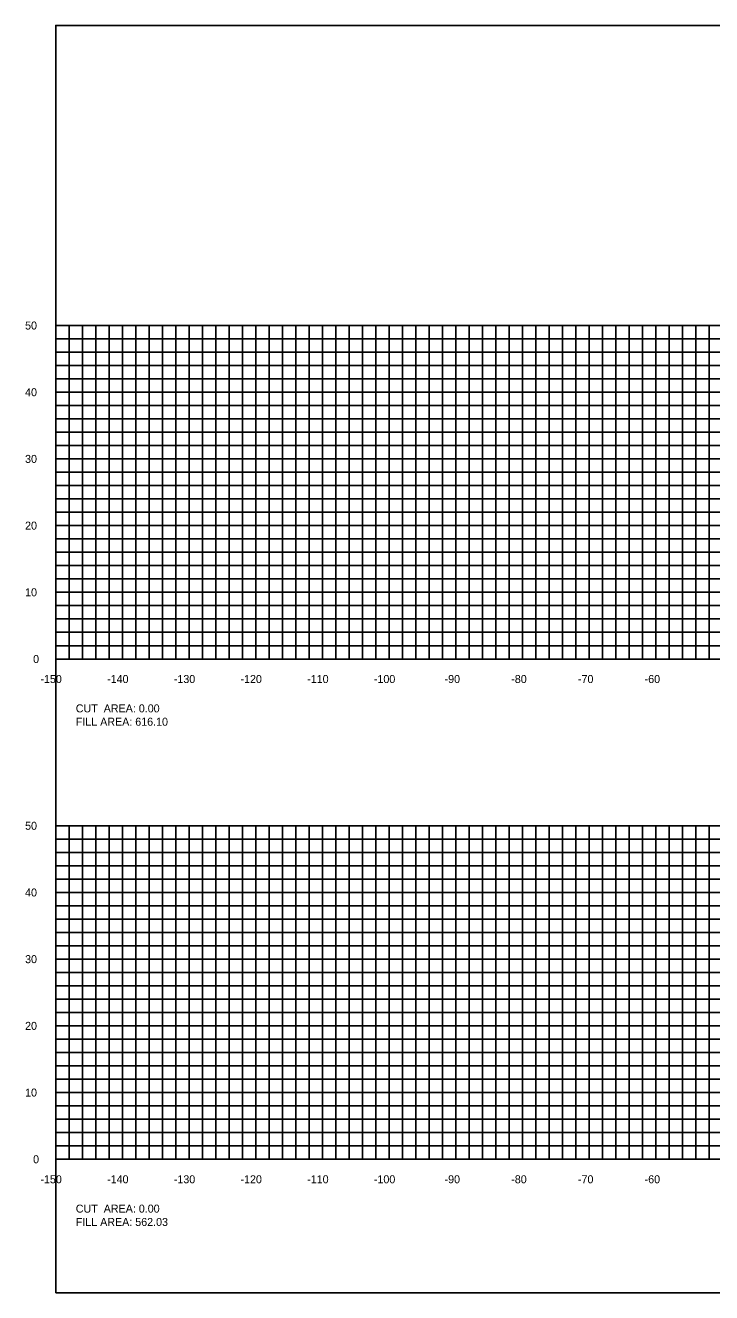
# Model space of a CAD drawing. Extents: x 1797714 to 1804825, y 249015 to 250269.
# Drawn here: x 1803156.4 to 1803259.4, y 250079.4 to 250269.4 of the extents above; entities that cross this region are included whole.
import ezdxf

# ---------------------------------------------------------------- set-up
doc = ezdxf.new("R2010")
doc.units = 0
for name, color, linetype in [('10', 7, 'Continuous'), ('31', 7, 'Continuous'), ('60', 7, 'Continuous'), ('ANNO-TXT', 7, 'Continuous'), ('Level 62', 7, 'Continuous')]:
    doc.layers.add(name, color=color, linetype=linetype)

msp = doc.modelspace()

# ---------------------------------------------------------------- linework, layer by layer
msp.add_lwpolyline([(1803161, 250079.43), (1803461, 250079.43), (1803461, 250269.43), (1803161, 250269.43)], close=True)
at = {"layer": '60'}
for p, q in [((1803160.94, 250224.43), (1803161, 250224.43)), ((1803161, 250174.43), (1803161, 250224.43)), ((1803160.94, 250214.43), (1803161, 250214.43)), ((1803160.94, 250204.43), (1803161, 250204.43)), ((1803160.94, 250194.43), (1803161, 250194.43)), ((1803160.94, 250184.43), (1803161, 250184.43)), ((1803160.94, 250174.43), (1803161, 250174.43)), ((1803161, 250174.43), (1803461, 250174.43)), ((1803161, 250174.37), (1803161, 250174.43)), ((1803171, 250174.37), (1803171, 250174.43)), ((1803181, 250174.37), (1803181, 250174.43)), ((1803191, 250174.37), (1803191, 250174.43)), ((1803201, 250174.37), (1803201, 250174.43)), ((1803211, 250174.37), (1803211, 250174.43)), ((1803221, 250174.37), (1803221, 250174.43)), ((1803231, 250174.37), (1803231, 250174.43)), ((1803241, 250174.37), (1803241, 250174.43)), ((1803251, 250174.37), (1803251, 250174.43)), ((1803160.94, 250149.43), (1803161, 250149.43)), ((1803161, 250099.43), (1803161, 250149.43)), ((1803160.94, 250139.43), (1803161, 250139.43)), ((1803160.94, 250129.43), (1803161, 250129.43)), ((1803160.94, 250119.43), (1803161, 250119.43)), ((1803160.94, 250109.43), (1803161, 250109.43)), ((1803160.94, 250099.43), (1803161, 250099.43)), ((1803161, 250099.43), (1803461, 250099.43)), ((1803161, 250099.37), (1803161, 250099.43)), ((1803171, 250099.37), (1803171, 250099.43)), ((1803181, 250099.37), (1803181, 250099.43)), ((1803191, 250099.37), (1803191, 250099.43)), ((1803201, 250099.37), (1803201, 250099.43)), ((1803211, 250099.37), (1803211, 250099.43)), ((1803221, 250099.37), (1803221, 250099.43)), ((1803231, 250099.37), (1803231, 250099.43)), ((1803241, 250099.37), (1803241, 250099.43)), ((1803251, 250099.37), (1803251, 250099.43))]:
    msp.add_line(p, q, dxfattribs=at)
at = {"layer": 'Level 62'}
for p, q in [((1803161, 250224.43), (1803461, 250224.43)), ((1803161, 250174.43), (1803161, 250224.43)), ((1803163, 250174.43), (1803163, 250224.43)), ((1803165, 250174.43), (1803165, 250224.43)), ((1803167, 250174.43), (1803167, 250224.43)), ((1803169, 250174.43), (1803169, 250224.43)), ((1803171, 250174.43), (1803171, 250224.43)), ((1803173, 250174.43), (1803173, 250224.43)), ((1803175, 250174.43), (1803175, 250224.43)), ((1803177, 250174.43), (1803177, 250224.43)), ((1803179, 250174.43), (1803179, 250224.43)), ((1803181, 250174.43), (1803181, 250224.43)), ((1803183, 250174.43), (1803183, 250224.43)), ((1803185, 250174.43), (1803185, 250224.43)), ((1803187, 250174.43), (1803187, 250224.43)), ((1803189, 250174.43), (1803189, 250224.43)), ((1803191, 250174.43), (1803191, 250224.43)), ((1803193, 250174.43), (1803193, 250224.43)), ((1803195, 250174.43), (1803195, 250224.43)), ((1803197, 250174.43), (1803197, 250224.43)), ((1803199, 250174.43), (1803199, 250224.43)), ((1803201, 250174.43), (1803201, 250224.43)), ((1803203, 250174.43), (1803203, 250224.43)), ((1803205, 250174.43), (1803205, 250224.43)), ((1803207, 250174.43), (1803207, 250224.43)), ((1803209, 250174.43), (1803209, 250224.43)), ((1803211, 250174.43), (1803211, 250224.43)), ((1803213, 250174.43), (1803213, 250224.43)), ((1803215, 250174.43), (1803215, 250224.43)), ((1803217, 250174.43), (1803217, 250224.43)), ((1803219, 250174.43), (1803219, 250224.43)), ((1803221, 250174.43), (1803221, 250224.43)), ((1803223, 250174.43), (1803223, 250224.43)), ((1803225, 250174.43), (1803225, 250224.43)), ((1803227, 250174.43), (1803227, 250224.43)), ((1803229, 250174.43), (1803229, 250224.43)), ((1803231, 250174.43), (1803231, 250224.43)), ((1803233, 250174.43), (1803233, 250224.43)), ((1803235, 250174.43), (1803235, 250224.43)), ((1803237, 250174.43), (1803237, 250224.43)), ((1803239, 250174.43), (1803239, 250224.43)), ((1803241, 250174.43), (1803241, 250224.43)), ((1803243, 250174.43), (1803243, 250224.43)), ((1803245, 250174.43), (1803245, 250224.43)), ((1803247, 250174.43), (1803247, 250224.43)), ((1803249, 250174.43), (1803249, 250224.43)), ((1803251, 250174.43), (1803251, 250224.43)), ((1803253, 250174.43), (1803253, 250224.43)), ((1803255, 250174.43), (1803255, 250224.43)), ((1803257, 250174.43), (1803257, 250224.43)), ((1803259, 250174.43), (1803259, 250224.43)), ((1803161, 250222.43), (1803461, 250222.43)), ((1803161, 250220.43), (1803461, 250220.43)), ((1803161, 250218.43), (1803461, 250218.43)), ((1803161, 250216.43), (1803461, 250216.43)), ((1803161, 250214.43), (1803461, 250214.43)), ((1803161, 250212.43), (1803461, 250212.43)), ((1803161, 250210.43), (1803461, 250210.43)), ((1803161, 250208.43), (1803461, 250208.43)), ((1803161, 250206.43), (1803461, 250206.43)), ((1803161, 250204.43), (1803461, 250204.43)), ((1803161, 250202.43), (1803461, 250202.43)), ((1803161, 250200.43), (1803461, 250200.43)), ((1803161, 250198.43), (1803461, 250198.43)), ((1803161, 250196.43), (1803461, 250196.43)), ((1803161, 250194.43), (1803461, 250194.43)), ((1803161, 250192.43), (1803461, 250192.43)), ((1803161, 250190.43), (1803461, 250190.43)), ((1803161, 250188.43), (1803461, 250188.43)), ((1803161, 250186.43), (1803461, 250186.43)), ((1803161, 250184.43), (1803461, 250184.43)), ((1803161, 250182.43), (1803461, 250182.43)), ((1803161, 250180.43), (1803461, 250180.43)), ((1803161, 250178.43), (1803461, 250178.43)), ((1803161, 250176.43), (1803461, 250176.43)), ((1803161, 250174.43), (1803461, 250174.43)), ((1803161, 250149.43), (1803461, 250149.43)), ((1803161, 250099.43), (1803161, 250149.43)), ((1803163, 250099.43), (1803163, 250149.43)), ((1803165, 250099.43), (1803165, 250149.43)), ((1803167, 250099.43), (1803167, 250149.43)), ((1803169, 250099.43), (1803169, 250149.43)), ((1803171, 250099.43), (1803171, 250149.43)), ((1803173, 250099.43), (1803173, 250149.43)), ((1803175, 250099.43), (1803175, 250149.43)), ((1803177, 250099.43), (1803177, 250149.43)), ((1803179, 250099.43), (1803179, 250149.43)), ((1803181, 250099.43), (1803181, 250149.43)), ((1803183, 250099.43), (1803183, 250149.43)), ((1803185, 250099.43), (1803185, 250149.43)), ((1803187, 250099.43), (1803187, 250149.43)), ((1803189, 250099.43), (1803189, 250149.43)), ((1803191, 250099.43), (1803191, 250149.43)), ((1803193, 250099.43), (1803193, 250149.43)), ((1803195, 250099.43), (1803195, 250149.43)), ((1803197, 250099.43), (1803197, 250149.43)), ((1803199, 250099.43), (1803199, 250149.43)), ((1803201, 250099.43), (1803201, 250149.43)), ((1803203, 250099.43), (1803203, 250149.43)), ((1803205, 250099.43), (1803205, 250149.43)), ((1803207, 250099.43), (1803207, 250149.43)), ((1803209, 250099.43), (1803209, 250149.43)), ((1803211, 250099.43), (1803211, 250149.43)), ((1803213, 250099.43), (1803213, 250149.43)), ((1803215, 250099.43), (1803215, 250149.43)), ((1803217, 250099.43), (1803217, 250149.43)), ((1803219, 250099.43), (1803219, 250149.43)), ((1803221, 250099.43), (1803221, 250149.43)), ((1803223, 250099.43), (1803223, 250149.43)), ((1803225, 250099.43), (1803225, 250149.43)), ((1803227, 250099.43), (1803227, 250149.43)), ((1803229, 250099.43), (1803229, 250149.43)), ((1803231, 250099.43), (1803231, 250149.43)), ((1803233, 250099.43), (1803233, 250149.43)), ((1803235, 250099.43), (1803235, 250149.43)), ((1803237, 250099.43), (1803237, 250149.43)), ((1803239, 250099.43), (1803239, 250149.43)), ((1803241, 250099.43), (1803241, 250149.43)), ((1803243, 250099.43), (1803243, 250149.43)), ((1803245, 250099.43), (1803245, 250149.43)), ((1803247, 250099.43), (1803247, 250149.43)), ((1803249, 250099.43), (1803249, 250149.43)), ((1803251, 250099.43), (1803251, 250149.43)), ((1803253, 250099.43), (1803253, 250149.43)), ((1803255, 250099.43), (1803255, 250149.43)), ((1803257, 250099.43), (1803257, 250149.43)), ((1803259, 250099.43), (1803259, 250149.43)), ((1803161, 250147.43), (1803461, 250147.43)), ((1803161, 250145.43), (1803461, 250145.43)), ((1803161, 250143.43), (1803461, 250143.43)), ((1803161, 250141.43), (1803461, 250141.43)), ((1803161, 250139.43), (1803461, 250139.43)), ((1803161, 250137.43), (1803461, 250137.43)), ((1803161, 250135.43), (1803461, 250135.43)), ((1803161, 250133.43), (1803461, 250133.43)), ((1803161, 250131.43), (1803461, 250131.43)), ((1803161, 250129.43), (1803461, 250129.43)), ((1803161, 250127.43), (1803461, 250127.43)), ((1803161, 250125.43), (1803461, 250125.43)), ((1803161, 250123.43), (1803461, 250123.43)), ((1803161, 250121.43), (1803461, 250121.43)), ((1803161, 250119.43), (1803461, 250119.43)), ((1803161, 250117.43), (1803461, 250117.43)), ((1803161, 250115.43), (1803461, 250115.43)), ((1803161, 250113.43), (1803461, 250113.43)), ((1803161, 250111.43), (1803461, 250111.43)), ((1803161, 250109.43), (1803461, 250109.43)), ((1803161, 250107.43), (1803461, 250107.43)), ((1803161, 250105.43), (1803461, 250105.43)), ((1803161, 250103.43), (1803461, 250103.43)), ((1803161, 250101.43), (1803461, 250101.43)), ((1803161, 250099.43), (1803461, 250099.43))]:
    msp.add_line(p, q, dxfattribs=at)

# ---------------------------------------------------------------- texts
at = {"layer": '10'}
for s, p in [('-150', (1803158.7, 250170.83)), ('-140', (1803168.7, 250170.83)), ('-130', (1803178.7, 250170.83)), ('-120', (1803188.7, 250170.83)), ('-110', (1803198.7, 250170.83)), ('-100', (1803208.7, 250170.83)), ('-90', (1803219.3, 250170.83)), ('-80', (1803229.3, 250170.83)), ('-70', (1803239.3, 250170.83)), ('-60', (1803249.3, 250170.83)), ('-150', (1803158.7, 250095.83)), ('-140', (1803168.7, 250095.83)), ('-130', (1803178.7, 250095.83)), ('-120', (1803188.7, 250095.83)), ('-110', (1803198.7, 250095.83)), ('-100', (1803208.7, 250095.83)), ('-90', (1803219.3, 250095.83)), ('-80', (1803229.3, 250095.83)), ('-70', (1803239.3, 250095.83)), ('-60', (1803249.3, 250095.83))]:
    msp.add_text(s, height=1.2, dxfattribs=at).set_placement(p)
at = {"layer": '31'}
for s, p in [('50', (1803156.4, 250223.83)), ('40', (1803156.4, 250213.83)), ('30', (1803156.4, 250203.83)), ('20', (1803156.4, 250193.83)), ('10', (1803156.4, 250183.83)), ('0', (1803157.6, 250173.83)), ('50', (1803156.4, 250148.83)), ('40', (1803156.4, 250138.83)), ('30', (1803156.4, 250128.83)), ('20', (1803156.4, 250118.83)), ('10', (1803156.4, 250108.83)), ('0', (1803157.6, 250098.83))]:
    msp.add_text(s, height=1.2, dxfattribs=at).set_placement(p)
at = {"layer": '60'}
for p in [(1803161, 250174.43), (1803161, 250099.43)]:
    msp.add_text('-', height=0.0001, dxfattribs=at).set_placement(p)
at = {"layer": 'ANNO-TXT'}
for s, p in [('CUT  AREA: 0.00', (1803164, 250166.43)), ('FILL AREA: 616.10', (1803164, 250164.43)), ('CUT  AREA: 0.00', (1803164, 250091.43)), ('FILL AREA: 562.03', (1803164, 250089.43))]:
    msp.add_text(s, height=1.2, dxfattribs=at).set_placement(p)

doc.saveas('drawing.dxf')
